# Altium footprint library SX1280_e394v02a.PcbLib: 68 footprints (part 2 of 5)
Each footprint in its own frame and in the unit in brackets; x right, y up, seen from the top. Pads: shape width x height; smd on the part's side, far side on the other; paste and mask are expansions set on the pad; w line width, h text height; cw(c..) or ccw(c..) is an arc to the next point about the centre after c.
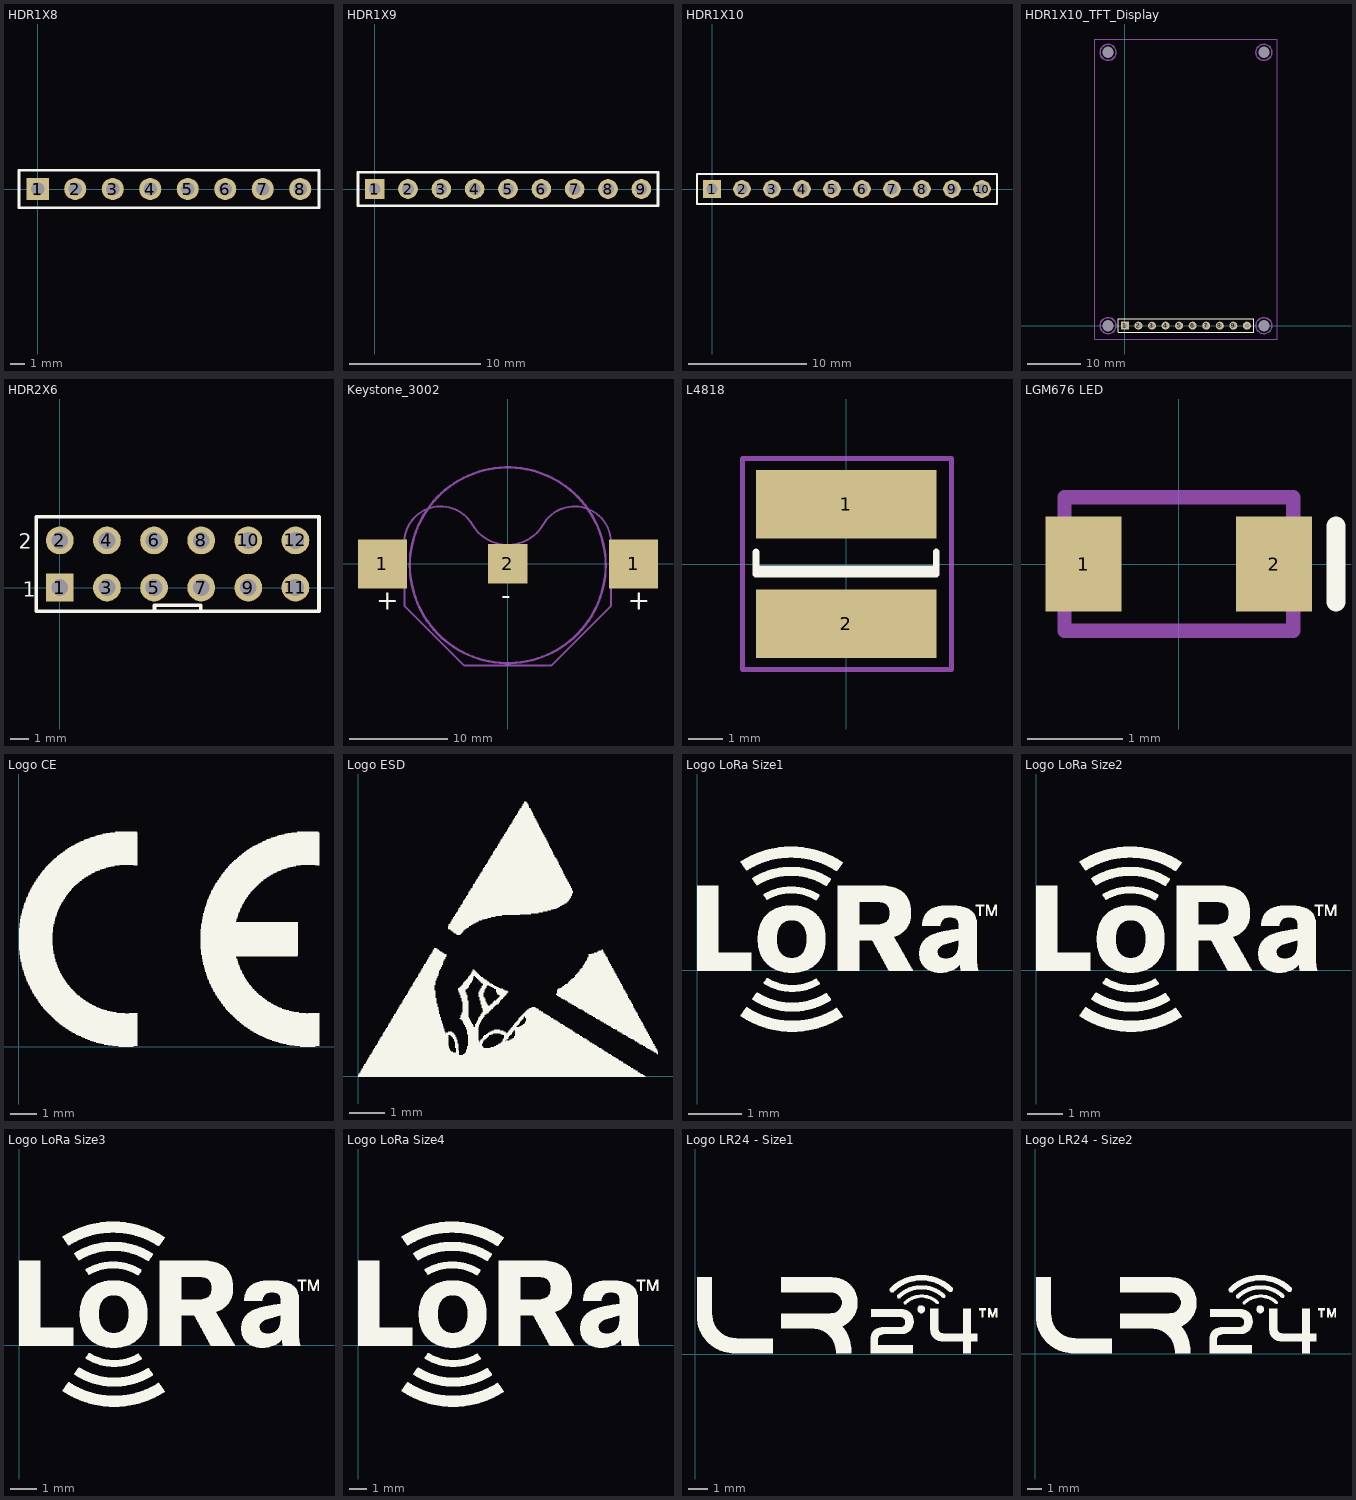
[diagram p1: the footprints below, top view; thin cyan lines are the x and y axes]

## HDR1X8 [mm] "Connector; Header; 8 Position"
pads (8):
  rect 1.5x1.5 hole 0.9: 1(0,0)
  round 1.5 hole 0.9: 2(2.54,0) 3(5.08,0) 4(7.62,0) 5(10.16,0) 6(12.7,0) 7(15.24,0) 8(17.78,0)
Top Overlay:
  lines w0.2: -1.27,-1.27 19.05,-1.27 19.05,1.27 -1.27,1.27 -1.27,-1.27

## HDR1X9 [mm] "Connector; Header; 9 Position"
pads (9):
  rect 1.5x1.5 hole 0.9: 1(0,0)
  round 1.5 hole 0.9: 2(2.54,0) 3(5.08,0) 4(7.62,0) 5(10.16,0) 6(12.7,0) 7(15.24,0) 8(17.78,0) 9(20.32,0)
Top Overlay:
  lines w0.2: -1.27,-1.27 -1.27,1.27 21.59,1.27 21.59,-1.27 -1.27,-1.27

## HDR1X10 [mm] "Connector; Header; 10 Position"
pads (10):
  rect 1.5x1.5 hole 0.9: 1(0,0)
  round 1.5 hole 0.9: 2(2.54,0) 3(5.08,0) 4(7.62,0) 5(10.16,0) 6(12.7,0) 7(15.24,0) 8(17.78,0) 9(20.32,0) 10(22.86,0)
Top Overlay:
  lines w0.2: -1.27,-1.27 24.13,-1.27 24.13,1.27 0.635,1.27 -1.27,1.27 -1.27,-1.27

## HDR1X10_TFT_Display [mm] "Connector; Header; 10 Position; Adafruit TFT Display"
pads (14):
  round 0 hole 2.1 unplated: 0(-3.15,51.2) 0(-3.15,0) 0(26.05,51.2) 0(26.05,0)
  rect 1.5x1.5 hole 0.9: 1(0,0)
  round 1.5 hole 0.9: 2(2.54,0) 3(5.08,0) 4(7.62,0) 5(10.16,0) 6(12.7,0) 7(15.24,0) 8(17.78,0) 9(20.32,0) 10(22.86,0)
Top Overlay:
  lines w0.2: -1.27,-1.27 -1.27,1.27 0.635,1.27 24.13,1.27 24.13,-1.27 -1.27,-1.27
Mechanical 15:
  circle w0.254: c26.05,51.2 r1.5
  circle w0.254: c26.05,0 r1.5
  circle w0.254: c-3.15,0 r1.5
  circle w0.254: c-3.15,51.2 r1.5
  lines w0.2: -4.15,0 -2.15,0 ; -4.15,51.2 -2.15,51.2 ; -3.15,-1 -3.15,1 ; -3.15,50.2 -3.15,52.2 ; 25.05,0 27.05,0 ; 25.05,51.2 27.05,51.2 ; 26.05,-1 26.05,1 ; 26.05,50.2 26.05,52.2 ; -5.65,-2.5 28.55,-2.5 28.55,53.7 -5.65,53.7 -5.65,-2.5

## HDR2X6 [mm] "Connector; Header; 6x2 Position"
pads (12):
  rect 1.5x1.5 hole 0.9: 1(0,0)
  round 1.5 hole 0.9: 2(0,2.54) 3(2.54,0) 4(2.54,2.54) 5(5.08,0) 6(5.08,2.54) 7(7.62,0) 8(7.62,2.54) 9(10.16,0) 10(10.16,2.54) 11(12.7,0) 12(12.7,2.54)
Top Overlay:
  lines w0.2: 5.1,-1.27 5.1,-0.95 7.6,-0.95 7.6,-1.27 ; -1.27,-1.27 13.97,-1.27 13.97,3.81 -1.27,3.81 -1.27,-1.27
  text "1" at -2,-0.5 h0.8
  text "2" at -2.2,2.1 h0.8

## Keystone_3002 [mm] "Keystone 3002 Battery Holder - CR2032 or other 20mm diam. battery"
height 3
pads (3):
  rect 5x5 smd mask+0.05: 1(-12.8,0) 1(12.85,0)
  rect 4x4 smd mask+0.05: 2(0,0)
Top Overlay:
  text "+" at -13.45,-4.7 h2
  text "+" at 12.25,-4.7 h2
  text "-" at -0.65,-4.2 h2
Mechanical 15:
  circle w0.254: c0,-0.15 r10.002
  lines w0.2: -10.568,-4.282 -4.45,-10.4 4.45,-10.4 10.55,-4.3 10.55,2.3 ccw(c6.832,2.147) 3.62,4.025 ; -10.568,-4.282 -10.568,2.235 -10.568,2.303 cw(c-6.85,2.15) -3.638,4.028 ccw(c0,6.15) 3.637,4.028

## L4818 [mil] "L4818"
height 196.85
pads (2):
  rect 209x79 smd mask+1.97: 1(0,69.03) 2(0,-69.03)
Top Overlay:
  lines w7.87: -104.33,-0.98 -104.33,-5.91 104.33,-5.91 ; -104.33,13.78 -104.33,-11.81 104.33,-11.81 104.33,13.78
Mechanical 15:
  lines w5.91: -120.08,-122.05 122.05,-122.05
  lines w6: -120.08,-122.05 -120.08,122.05 122.05,122.05 122.05,-122.05

## LGM676 LED [mm] "Chip Diode; Body 2.1 x 1.4 mm (LxW typ)"
height 1.1
pads (2):
  rect 0.8x1 smd mask+0.05: 1(-1,0) 2(1,0)
Top Overlay:
  lines w0.2: 1.65,-0.4 1.65,0.4
Mechanical 15:
  lines w0.15: -1.2,-0.7 1.2,-0.7 1.2,0.7 -1.2,0.7 -1.2,-0.7
3D body: height 12, standoff 0, extent -1.2,-0.7 1.2,0.7

## Logo CE [mm] "Logo CE"
height 0.1
Top Overlay:
  drawing of 654 lines, arcs and shapes, not listed

## Logo ESD [mm] "Logo ESD"
height 0.1
Top Overlay:
  drawing of 682 lines, arcs and shapes, not listed

## Logo LoRa Size1 [mm] "Logo LoRa Size1 - Top Overlay"
Top Overlay:
  drawing of 2375 lines, arcs and shapes, not listed

## Logo LoRa Size2 [mm] "Logo LoRa Size2 - Top Overlay"
Top Overlay:
  drawing of 2374 lines, arcs and shapes, not listed

## Logo LoRa Size3 [mm] "Logo LoRa Size3 - Top Overlay"
Top Overlay:
  drawing of 2375 lines, arcs and shapes, not listed

## Logo LoRa Size4 [mm] "Logo LoRa Size4 - Top Overlay"
Top Overlay:
  drawing of 2375 lines, arcs and shapes, not listed

## Logo LR24 - Size1 [mm] "Logo LR24 - Size1 - Top Overlay"
Top Overlay:
  drawing of 1244 lines, arcs and shapes, not listed

## Logo LR24 - Size2 [mm] "Logo LR24 - Size2 - Top Overlay"
Top Overlay:
  drawing of 1244 lines, arcs and shapes, not listed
